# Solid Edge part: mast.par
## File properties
Author: Cymax
Template: Normal.par
Last saved by: haldur
Revision: 14
Application: Solid Edge
Accuracy: 0,990
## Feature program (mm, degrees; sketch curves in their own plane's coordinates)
sketch for "unnamed Protrusion 1" plane through (0, 0, 0) normal (0, 0, 1) x-axis (1, 0, 0)
  circle centre (0, 0) radius 75
extrude "unnamed Protrusion 1" add finite 9000 symmetric
sketch for "ExtrudedProtrusion_2" plane through (0, 0, 0) normal (1, 0, 0) x-axis (0, 1, 0)
  circle centre (0, -2150) radius 75
extrude "ExtrudedProtrusion_2" add finite 3250 along +normal
sketch for "ExtrudedProtrusion_3" plane through (0, 0, -2150) normal (0, 0, 1) x-axis (1, 0, 0)
  circle centre (208.2532, 0) radius 15
extrude "ExtrudedProtrusion_3" add finite 142.6344 along +normal
sketch for "RevolvedProtrusion_2" plane through (0, -15, 0) normal (0, -1, 0) x-axis (1, 0, 0)
  circle centre (208.2532, -2007.3656) radius 15
revolve "RevolvedProtrusion_2" add finite 270 deg about sketch line (193.2532, -1960.2573) -> (223.2532, -1960.2573)
fillet "Round_7" radius 15
pattern "Pattern_2" of "RevolvedProtrusion_2", "ExtrudedProtrusion_3" along a curve  XDirCount = 10
extrude "unnamed Protrusion 2" add finite 142.6344
revolve "unnamed RevolvedProtrusion 1" add finite 270 deg
extrude "unnamed Protrusion 3" add finite 142.6344
revolve "unnamed RevolvedProtrusion 2" add finite 270 deg
extrude "unnamed Protrusion 4" add finite 142.6344
revolve "unnamed RevolvedProtrusion 3" add finite 270 deg
extrude "unnamed Protrusion 5" add finite 142.6344
revolve "unnamed RevolvedProtrusion 4" add finite 270 deg
extrude "unnamed Protrusion 6" add finite 142.6344
revolve "unnamed RevolvedProtrusion 5" add finite 270 deg
extrude "unnamed Protrusion 7" add finite 142.6344
revolve "unnamed RevolvedProtrusion 6" add finite 270 deg
extrude "unnamed Protrusion 8" add finite 142.6344
revolve "unnamed RevolvedProtrusion 7" add finite 270 deg
extrude "unnamed Protrusion 9" add finite 142.6344
revolve "unnamed RevolvedProtrusion 8" add finite 270 deg
extrude "unnamed Protrusion 10" add finite 142.6344
revolve "unnamed RevolvedProtrusion 9" add finite 270 deg
sketch for "ExtrudedProtrusion_19" plane through (0, 0, 0) normal (1, 0, 0) x-axis (0, 1, 0)
  circle centre (0, -1452.6) radius 15
extrude "ExtrudedProtrusion_19" add finite 120 along +normal
sketch for "RevolvedProtrusion_18" plane through (0, -15, 0) normal (0, -1, 0) x-axis (1, 0, 0)
  circle centre (120, -1452.6) radius 15
revolve "RevolvedProtrusion_18" add finite 270 deg about sketch line (158.9689, -1437.6) -> (158.9689, -1467.6)
fillet "Round_8" radius 12
pattern "Pattern_3" of "RevolvedProtrusion_18", "ExtrudedProtrusion_19" along a curve  XDirCount = 10
extrude "unnamed Protrusion 11" add finite 120
revolve "unnamed RevolvedProtrusion 10" add finite 270 deg
extrude "unnamed Protrusion 12" add finite 120
revolve "unnamed RevolvedProtrusion 11" add finite 270 deg
extrude "unnamed Protrusion 13" add finite 120
revolve "unnamed RevolvedProtrusion 12" add finite 270 deg
extrude "unnamed Protrusion 14" add finite 120
revolve "unnamed RevolvedProtrusion 13" add finite 270 deg
extrude "unnamed Protrusion 15" add finite 120
revolve "unnamed RevolvedProtrusion 14" add finite 270 deg
extrude "unnamed Protrusion 16" add finite 120
revolve "unnamed RevolvedProtrusion 15" add finite 270 deg
extrude "unnamed Protrusion 17" add finite 120
revolve "unnamed RevolvedProtrusion 16" add finite 270 deg
extrude "unnamed Protrusion 18" add finite 120
revolve "unnamed RevolvedProtrusion 17" add finite 270 deg
extrude "unnamed Protrusion 19" add finite 120
revolve "unnamed RevolvedProtrusion 18" add finite 270 deg
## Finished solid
Body 1: solid body, 126 faces, 206 edges, 102 vertices.
  Faces by surface: plane 82, cylinder 22, torus 20, blend 1, sphere 1
  Edges by curve: intersection 122, circle 82, ellipse 2
Bounding box of the edges (mm; curved faces can reach further): 3325.000 x 152.108 x 9000.000, from (-75, -77.1083, -4500) to (3250, 75, 4500).
Cylindrical faces by radius (mm): R15 x20, R75 x2
Toroidal faces (ring radius, tube radius in mm): R38.9689 r15 x10, R47.1083 r15 x10
Spherical faces by radius (mm): R15 x1
Planar faces by outward normal: +x 21, +z 21, -x 10, -y 20, -z 10
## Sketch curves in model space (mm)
line (0, 0, 3957.0189) -> (0, 0, -1452.6)
line (207.3865, 0, -2150) -> (2950.2528, 0, -2150)
circle centre (0, 0, -2150) radius 75
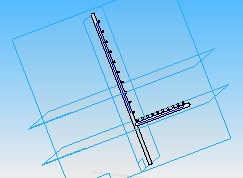
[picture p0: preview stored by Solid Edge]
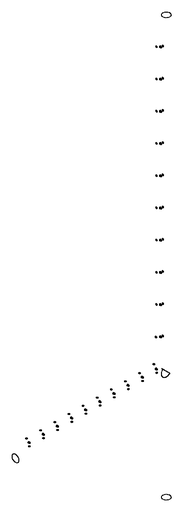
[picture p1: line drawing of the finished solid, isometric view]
